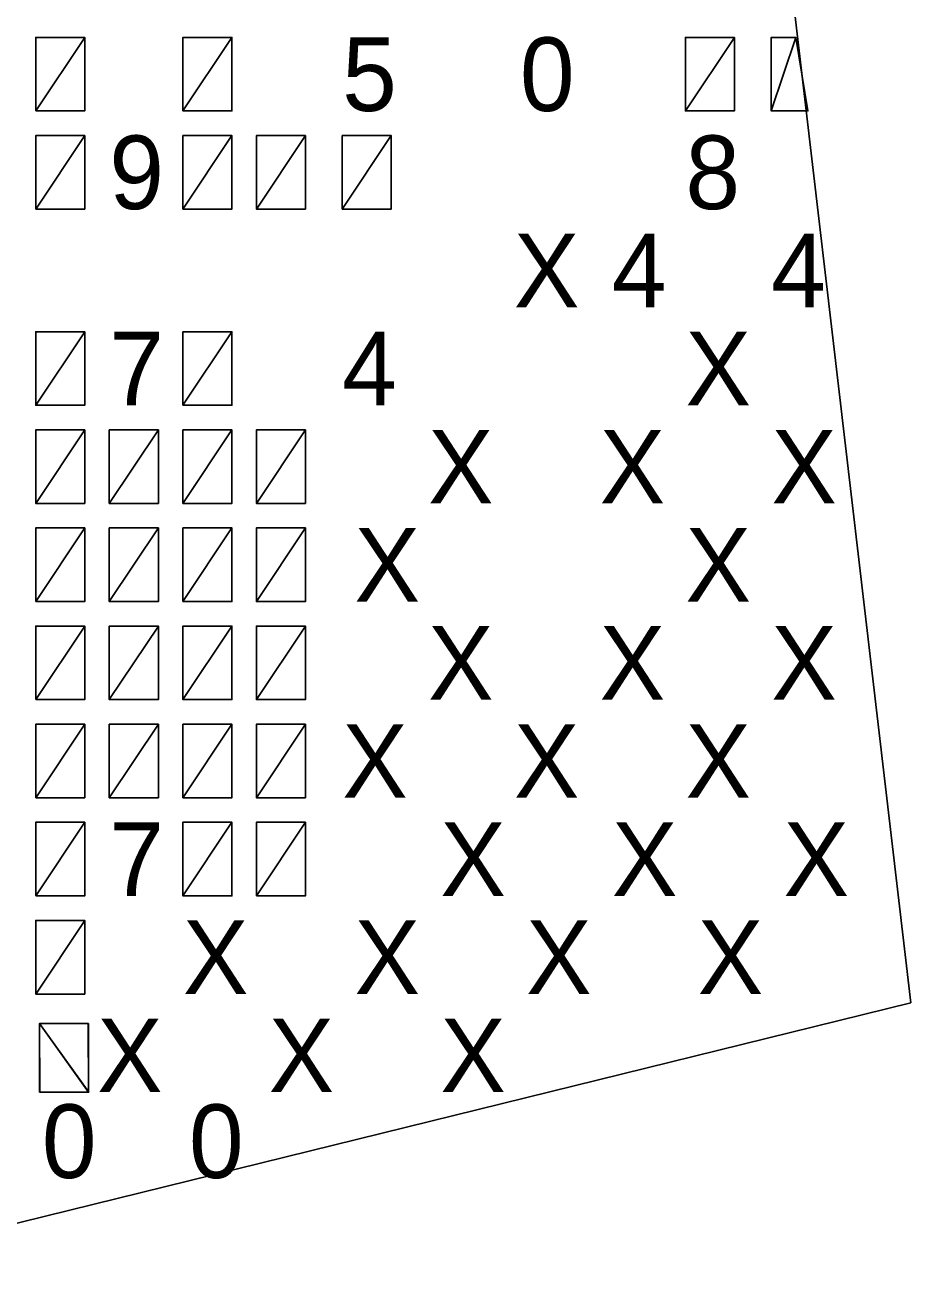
# Model space of a CAD drawing. Extents: x -10 to 89.7, y -4.8 to 22.
# Drawn here: x 2.5039 to 2.7095, y 1.4466 to 1.7377 of the extents above; entities that cross this region are included whole.
import ezdxf

# ---------------------------------------------------------------- set-up
doc = ezdxf.new("R2010")
doc.units = 0
doc.layers.add('Default', color=7, linetype='Continuous')

msp = doc.modelspace()

# ---------------------------------------------------------------- linework, layer by layer
at = {"layer": 'Default'}
for p, q in [((2.65109, 2.00807), (2.70953, 1.5109)), ((2.51777, 1.73489), (2.50639, 1.73489)), ((2.50639, 1.73489), (2.50639, 1.71781)), ((2.51777, 1.71781), (2.51777, 1.73489)), ((2.54054, 1.73489), (2.54054, 1.71781)), ((2.55192, 1.73489), (2.54054, 1.73489)), ((2.55192, 1.71781), (2.55192, 1.73489)), ((2.66857, 1.73489), (2.65719, 1.73489)), ((2.65719, 1.73489), (2.65719, 1.71781)), ((2.66857, 1.71781), (2.66857, 1.73489)), ((2.67711, 1.73489), (2.6828, 1.73489)), ((2.67711, 1.71781), (2.67711, 1.73489)), ((2.50639, 1.71781), (2.51777, 1.71781)), ((2.54054, 1.71781), (2.55192, 1.71781)), ((2.65719, 1.71781), (2.66857, 1.71781)), ((2.67711, 1.71781), (2.68564, 1.71781)), ((2.50639, 1.71212), (2.50639, 1.69505)), ((2.51777, 1.71212), (2.50639, 1.71212)), ((2.51777, 1.69505), (2.51777, 1.71212)), ((2.55192, 1.71212), (2.54054, 1.71212)), ((2.54054, 1.71212), (2.54054, 1.69505)), ((2.55192, 1.69505), (2.55192, 1.71212)), ((2.55761, 1.71212), (2.55761, 1.69505)), ((2.56899, 1.71212), (2.55761, 1.71212)), ((2.56899, 1.69505), (2.56899, 1.71212)), ((2.5889, 1.71212), (2.57752, 1.71212)), ((2.57752, 1.71212), (2.57752, 1.69505)), ((2.5889, 1.69505), (2.5889, 1.71212)), ((2.50639, 1.69505), (2.51777, 1.69505)), ((2.54054, 1.69505), (2.55192, 1.69505)), ((2.55761, 1.69505), (2.56899, 1.69505)), ((2.57752, 1.69505), (2.5889, 1.69505)), ((2.51777, 1.6666), (2.50639, 1.6666)), ((2.50639, 1.6666), (2.50639, 1.64953)), ((2.51777, 1.64953), (2.51777, 1.6666)), ((2.54054, 1.6666), (2.54054, 1.64953)), ((2.55192, 1.6666), (2.54054, 1.6666)), ((2.55192, 1.64953), (2.55192, 1.6666)), ((2.50639, 1.64953), (2.51777, 1.64953)), ((2.54054, 1.64953), (2.55192, 1.64953)), ((2.50639, 1.64384), (2.50639, 1.62677)), ((2.51777, 1.64384), (2.50639, 1.64384)), ((2.51777, 1.62677), (2.51777, 1.64384)), ((2.53485, 1.64384), (2.52347, 1.64384)), ((2.52347, 1.64384), (2.52347, 1.62677)), ((2.53485, 1.62677), (2.53485, 1.64384)), ((2.55192, 1.64384), (2.54054, 1.64384)), ((2.54054, 1.64384), (2.54054, 1.62677)), ((2.55192, 1.62677), (2.55192, 1.64384)), ((2.55761, 1.64384), (2.55761, 1.62677)), ((2.56899, 1.64384), (2.55761, 1.64384)), ((2.56899, 1.62677), (2.56899, 1.64384)), ((2.50639, 1.62677), (2.51777, 1.62677)), ((2.52347, 1.62677), (2.53485, 1.62677)), ((2.54054, 1.62677), (2.55192, 1.62677)), ((2.55761, 1.62677), (2.56899, 1.62677)), ((2.50639, 1.62108), (2.50639, 1.60401)), ((2.51777, 1.62108), (2.50639, 1.62108)), ((2.51777, 1.60401), (2.51777, 1.62108)), ((2.52347, 1.62108), (2.52347, 1.60401)), ((2.53485, 1.62108), (2.52347, 1.62108)), ((2.53485, 1.60401), (2.53485, 1.62108)), ((2.55192, 1.62108), (2.54054, 1.62108)), ((2.54054, 1.62108), (2.54054, 1.60401)), ((2.55192, 1.60401), (2.55192, 1.62108)), ((2.56899, 1.62108), (2.55761, 1.62108)), ((2.55761, 1.62108), (2.55761, 1.60401)), ((2.56899, 1.60401), (2.56899, 1.62108)), ((2.50639, 1.60401), (2.51777, 1.60401)), ((2.52347, 1.60401), (2.53485, 1.60401)), ((2.54054, 1.60401), (2.55192, 1.60401)), ((2.55761, 1.60401), (2.56899, 1.60401)), ((2.51777, 1.59832), (2.50639, 1.59832)), ((2.50639, 1.59832), (2.50639, 1.58125)), ((2.51777, 1.58125), (2.51777, 1.59832)), ((2.53485, 1.59832), (2.52347, 1.59832)), ((2.52347, 1.59832), (2.52347, 1.58125)), ((2.53485, 1.58125), (2.53485, 1.59832)), ((2.54054, 1.59832), (2.54054, 1.58125)), ((2.55192, 1.59832), (2.54054, 1.59832)), ((2.55192, 1.58125), (2.55192, 1.59832)), ((2.56899, 1.59832), (2.55761, 1.59832)), ((2.55761, 1.59832), (2.55761, 1.58125)), ((2.56899, 1.58125), (2.56899, 1.59832)), ((2.50639, 1.58125), (2.51777, 1.58125)), ((2.52347, 1.58125), (2.53485, 1.58125)), ((2.54054, 1.58125), (2.55192, 1.58125)), ((2.55761, 1.58125), (2.56899, 1.58125)), ((2.50639, 1.57556), (2.50639, 1.55848)), ((2.51777, 1.57556), (2.50639, 1.57556)), ((2.51777, 1.55848), (2.51777, 1.57556)), ((2.52347, 1.57556), (2.52347, 1.55848)), ((2.53485, 1.57556), (2.52347, 1.57556)), ((2.53485, 1.55848), (2.53485, 1.57556)), ((2.55192, 1.57556), (2.54054, 1.57556)), ((2.54054, 1.57556), (2.54054, 1.55848)), ((2.55192, 1.55848), (2.55192, 1.57556)), ((2.55761, 1.57556), (2.55761, 1.55848)), ((2.56899, 1.57556), (2.55761, 1.57556)), ((2.56899, 1.55848), (2.56899, 1.57556)), ((2.50639, 1.55848), (2.51777, 1.55848)), ((2.52347, 1.55848), (2.53485, 1.55848)), ((2.54054, 1.55848), (2.55192, 1.55848)), ((2.55761, 1.55848), (2.56899, 1.55848)), ((2.51777, 1.55279), (2.50639, 1.55279)), ((2.50639, 1.55279), (2.50639, 1.53572)), ((2.51777, 1.53572), (2.51777, 1.55279)), ((2.55192, 1.55279), (2.54054, 1.55279)), ((2.54054, 1.55279), (2.54054, 1.53572)), ((2.55192, 1.53572), (2.55192, 1.55279)), ((2.55761, 1.55279), (2.55761, 1.53572)), ((2.56899, 1.55279), (2.55761, 1.55279)), ((2.56899, 1.53572), (2.56899, 1.55279)), ((2.50639, 1.53572), (2.51777, 1.53572)), ((2.54054, 1.53572), (2.55192, 1.53572)), ((2.55761, 1.53572), (2.56899, 1.53572)), ((2.50639, 1.53003), (2.50639, 1.51296)), ((2.51777, 1.53003), (2.50639, 1.53003)), ((2.51777, 1.51296), (2.51777, 1.53003)), ((2.70953, 1.5109), (2.44872, 1.44664)), ((2.50639, 1.51296), (2.51777, 1.51296)), ((2.50725, 1.50611), (2.50725, 1.4902)), ((2.50726, 1.50611), (2.51862, 1.50611)), ((2.51863, 1.4902), (2.51863, 1.50611)), ((2.50725, 1.4902), (2.51863, 1.4902))]:
    msp.add_line(p, q, dxfattribs=at)
for points in [[(2.50639, 1.71781), (2.51777, 1.71781), (2.51777, 1.73489)], [(2.50639, 1.71781), (2.50639, 1.73489), (2.51777, 1.73489)], [(2.54054, 1.71781), (2.54054, 1.73489), (2.55192, 1.73489)], [(2.55192, 1.73489), (2.55192, 1.71781), (2.54054, 1.71781)], [(2.55192, 1.73489), (2.55192, 1.73489), (2.55192, 1.73489)], [(2.65719, 1.71781), (2.65719, 1.73489), (2.66857, 1.73489)], [(2.66857, 1.73489), (2.66857, 1.71781), (2.65719, 1.71781)], [(2.67711, 1.71781), (2.67711, 1.73489), (2.6828, 1.73489)], [(2.6828, 1.73489), (2.68564, 1.71781), (2.67711, 1.71781)], [(2.50639, 1.69505), (2.50639, 1.71212), (2.51777, 1.71212)], [(2.50639, 1.69505), (2.51777, 1.69505), (2.51777, 1.71212)], [(2.55192, 1.71212), (2.55192, 1.69505), (2.54054, 1.69505)], [(2.54054, 1.69505), (2.54054, 1.71212), (2.55192, 1.71212)], [(2.55192, 1.71212), (2.55192, 1.71212), (2.55192, 1.71212)], [(2.56899, 1.71212), (2.56899, 1.69505), (2.55761, 1.69505)], [(2.55761, 1.69505), (2.55761, 1.71212), (2.56899, 1.71212)], [(2.57752, 1.69505), (2.57752, 1.71212), (2.5889, 1.71212)], [(2.5889, 1.71212), (2.5889, 1.69505), (2.57752, 1.69505)], [(2.50639, 1.64953), (2.50639, 1.6666), (2.51777, 1.6666)], [(2.51777, 1.6666), (2.51777, 1.64953), (2.50639, 1.64953)], [(2.54054, 1.64953), (2.54054, 1.6666), (2.55192, 1.6666)], [(2.54054, 1.64953), (2.55192, 1.64953), (2.55192, 1.6666)], [(2.51777, 1.64384), (2.51777, 1.62677), (2.50639, 1.62677)], [(2.50639, 1.62677), (2.50639, 1.64384), (2.51777, 1.64384)], [(2.52347, 1.62677), (2.53485, 1.62677), (2.53485, 1.64384)], [(2.52347, 1.62677), (2.52347, 1.64384), (2.53485, 1.64384)], [(2.54054, 1.62677), (2.55192, 1.62677), (2.55192, 1.64384)], [(2.54054, 1.62677), (2.54054, 1.64384), (2.55192, 1.64384)], [(2.56899, 1.64384), (2.56899, 1.62677), (2.55761, 1.62677)], [(2.55761, 1.62677), (2.55761, 1.64384), (2.56899, 1.64384)], [(2.50639, 1.60401), (2.50639, 1.62108), (2.51777, 1.62108)], [(2.50639, 1.60401), (2.51777, 1.60401), (2.51777, 1.62108)], [(2.53485, 1.62108), (2.53485, 1.60401), (2.52347, 1.60401)], [(2.52347, 1.60401), (2.52347, 1.62108), (2.53485, 1.62108)], [(2.54054, 1.60401), (2.55192, 1.60401), (2.55192, 1.62108)], [(2.54054, 1.60401), (2.54054, 1.62108), (2.55192, 1.62108)], [(2.55761, 1.60401), (2.55761, 1.62108), (2.56899, 1.62108)], [(2.56899, 1.62108), (2.56899, 1.60401), (2.55761, 1.60401)], [(2.50639, 1.58125), (2.51777, 1.58125), (2.51777, 1.59832)], [(2.50639, 1.58125), (2.50639, 1.59832), (2.51777, 1.59832)], [(2.53485, 1.59832), (2.53485, 1.58125), (2.52347, 1.58125)], [(2.52347, 1.58125), (2.52347, 1.59832), (2.53485, 1.59832)], [(2.53485, 1.59832), (2.53485, 1.59832), (2.53485, 1.59832)], [(2.54054, 1.58125), (2.54054, 1.59832), (2.55192, 1.59832)], [(2.55192, 1.59832), (2.55192, 1.58125), (2.54054, 1.58125)], [(2.55192, 1.59832), (2.55192, 1.59832), (2.55192, 1.59832)], [(2.55761, 1.58125), (2.55761, 1.59832), (2.56899, 1.59832)], [(2.56899, 1.59832), (2.56899, 1.58125), (2.55761, 1.58125)], [(2.50639, 1.55848), (2.50639, 1.57556), (2.51777, 1.57556)], [(2.50639, 1.55848), (2.51777, 1.55848), (2.51777, 1.57556)], [(2.52347, 1.55848), (2.52347, 1.57556), (2.53485, 1.57556)], [(2.53485, 1.57556), (2.53485, 1.55848), (2.52347, 1.55848)], [(2.53485, 1.57556), (2.53485, 1.57556), (2.53485, 1.57556)], [(2.55192, 1.57556), (2.55192, 1.55848), (2.54054, 1.55848)], [(2.54054, 1.55848), (2.54054, 1.57556), (2.55192, 1.57556)], [(2.55192, 1.57556), (2.55192, 1.57556), (2.55192, 1.57556)], [(2.56899, 1.57556), (2.56899, 1.55848), (2.55761, 1.55848)], [(2.55761, 1.55848), (2.55761, 1.57556), (2.56899, 1.57556)], [(2.50639, 1.53572), (2.51777, 1.53572), (2.51777, 1.55279)], [(2.50639, 1.53572), (2.50639, 1.55279), (2.51777, 1.55279)], [(2.54054, 1.53572), (2.54054, 1.55279), (2.55192, 1.55279)], [(2.55192, 1.55279), (2.55192, 1.53572), (2.54054, 1.53572)], [(2.55761, 1.53572), (2.55761, 1.55279), (2.56899, 1.55279)], [(2.55761, 1.53572), (2.56899, 1.53572), (2.56899, 1.55279)], [(2.50639, 1.51296), (2.50639, 1.53003), (2.51777, 1.53003)], [(2.50639, 1.51296), (2.51777, 1.51296), (2.51777, 1.53003)], [(2.50726, 1.50611), (2.51855, 1.50611), (2.51862, 1.49015)], [(2.50733, 1.49026), (2.51869, 1.49015), (2.50726, 1.50611)], [(2.51862, 1.49015), (2.51862, 1.49015), (2.51869, 1.49015), (2.50733, 1.49026)]]:
    msp.add_lwpolyline(points, close=True, dxfattribs=at)

# ---------------------------------------------------------------- texts
for s, p in [('0', (2.61878, 1.71781)), ('5', (2.57752, 1.71781)), ('9', (2.52347, 1.69505)), ('8', (2.65719, 1.69505)), ('X', (2.61736, 1.67229)), ('4', (2.64012, 1.67229)), ('4', (2.67711, 1.67229)), ('7', (2.52347, 1.64953)), ('4', (2.57752, 1.64953)), ('X', (2.65719, 1.64953)), ('X', (2.59744, 1.62677)), ('X', (2.63727, 1.62677)), ('X', (2.67711, 1.62677)), ('X', (2.58037, 1.60401)), ('X', (2.65719, 1.60401)), ('X', (2.59744, 1.58125)), ('X', (2.63727, 1.58125)), ('X', (2.67711, 1.58125)), ('X', (2.57752, 1.55848)), ('X', (2.61736, 1.55848)), ('X', (2.65719, 1.55848)), ('7', (2.52347, 1.53572)), ('X', (2.60029, 1.53572)), ('X', (2.64012, 1.53572)), ('X', (2.67995, 1.53572)), ('X', (2.54054, 1.51296)), ('X', (2.58037, 1.51296)), ('X', (2.6202, 1.51296)), ('X', (2.66003, 1.51296)), ('X', (2.52062, 1.4902)), ('X', (2.56045, 1.4902)), ('X', (2.60029, 1.4902)), ('0', (2.50782, 1.47028)), ('0', (2.54196, 1.47028))]:
    msp.add_text(s, height=0.01707, dxfattribs=at).set_placement(p)

doc.saveas('drawing.dxf')
